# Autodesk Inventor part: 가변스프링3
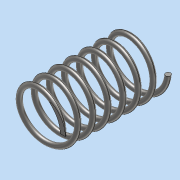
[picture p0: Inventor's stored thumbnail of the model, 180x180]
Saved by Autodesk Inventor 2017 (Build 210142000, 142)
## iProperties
Part Number: 가변스프링3
Material: 스테인레스 스틸
Document SubType Name: Modeling
Designer: MRC
Density: 8 g/cm^3
Appearance: 반연마
Mass: 10.9961 g
Surface Area: 27.6971 cm^2
Volume: 1.37451 cm^3
Author: MRC
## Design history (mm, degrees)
sketch "스케치1"
  geometry: L1 (0, 41.411)-(10, 41.411); L2 (10, 41.411)-(10, 0); L3 (10, 0)-(0, 0); L4 (0, 0)-(0, 41.411); C1 r 1 at (10, 0); 1 further point
  constraints: 8 end point, 2 coincident, 2 parallel, 1 centre point, 1 horizontal, 1 perpendicular
  dimensions: "d0" = 41.4112 distance of L1.end L2.end (derived); "d1" = 20 diameter of L2 L4; "d2" = 2 diameter of C1
feature "코일1" sketch "스케치1" pitch "d3" = 10; turns "d5" = 7; dims "d4" = 41.4112 (= d0), "d6" = 0, angle "d7" = 90 deg, angle "d8" = 90 deg, "d9" = 0, "d10" = 0
sketch "스케치2"
  geometry: L1 (-19.444, 50)-(19.444, 50); L2 (19.444, 50)-(19.444, 0); L3 (19.444, 0)-(-19.444, 0); L4 (-19.444, 0)-(-19.444, 50); 2 further points
  constraints: 8 end point, 2 parallel, 1 coincident, 1 horizontal, 1 midpoint, 1 perpendicular
  dimensions: "d11" = 50 distance of L1.end L2.end; "d12" = 38.88889 distance of L1.start L1.end
extrude "돌출1" sketch "스케치2" stored distance "d13" = 0; taper "d14" = 0 deg
node "솔리드1"
